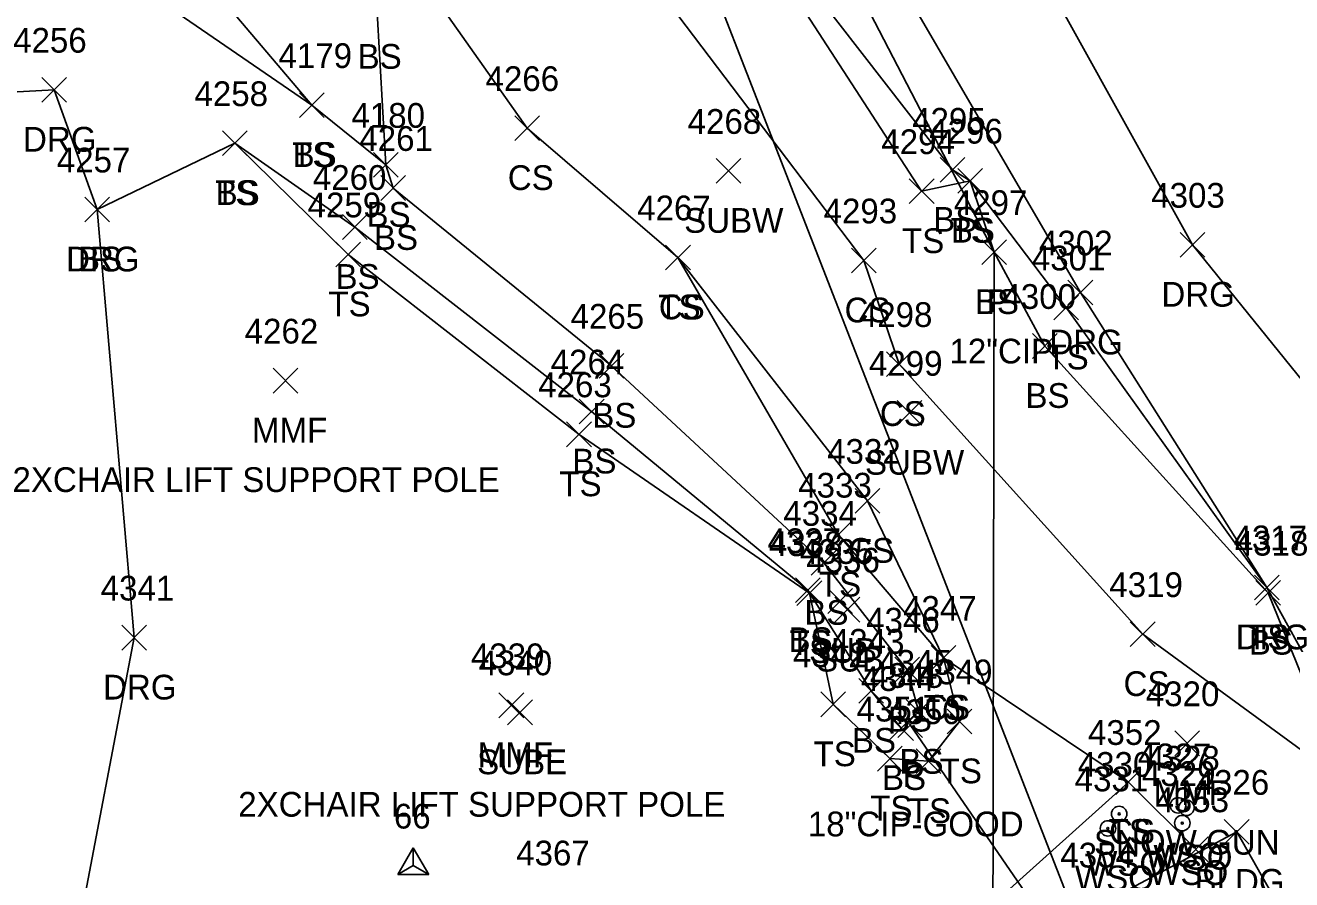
# Model space of a CAD drawing. Extents: x 49137 to 50946, y 9590 to 10709.
# Drawn here: x 50101.6 to 50204, y 10501.9 to 10570.9 of the extents above; entities that cross this region are included whole.
import ezdxf

# ---------------------------------------------------------------- set-up
doc = ezdxf.new("R2010")
doc.units = 0
for name, color, linetype in [('C_I', 7, 'Continuous'), ('CPSM', 7, 'Continuous'), ('D_A', 7, 'Continuous'), ('D_C', 7, 'Continuous'), ('D_I', 7, 'Continuous'), ('D_TIC', 7, 'Continuous'), ('DCP', 7, 'Continuous'), ('L_A', 7, 'Continuous'), ('L_C', 7, 'Continuous'), ('L_I', 7, 'Continuous'), ('L_TIC', 7, 'Continuous'), ('LBC', 7, 'Continuous'), ('LELB', 7, 'Continuous'), ('R_A', 7, 'Continuous'), ('R_I', 7, 'Continuous'), ('R_TIC', 7, 'Continuous'), ('RDG', 7, 'Continuous'), ('U_A', 7, 'Continuous'), ('U_I', 7, 'Continuous'), ('U_TIC', 7, 'Continuous'), ('UWV', 7, 'Continuous')]:
    doc.layers.add(name, color=color, linetype=linetype)

msp = doc.modelspace()

# ---------------------------------------------------------------- linework, layer by layer
at = {"layer": 'CPSM'}
for p, q in [((50131.72, 10502.3), (50132.97, 10504.46)), ((50134.22, 10502.3), (50132.97, 10504.46)), ((50132.97, 10503.02), (50132.97, 10504.46)), ((50131.72, 10502.3), (50132.97, 10503.02)), ((50132.97, 10503.02), (50132.97, 10503.02)), ((50132.97, 10503.02), (50134.22, 10502.3)), ((50131.72, 10502.3), (50134.22, 10502.3))]:
    msp.add_line(p, q, dxfattribs=at)
at = {"layer": 'D_TIC'}
for points in [[(50178.93, 10551.61), (50180.93, 10553.61)], [(50180.93, 10551.61), (50178.93, 10553.61)], [(50172.14, 10513.39), (50174.14, 10515.39)], [(50174.14, 10513.39), (50172.14, 10515.39)]]:
    msp.add_lwpolyline(points, dxfattribs=at)
at = {"layer": 'DCP'}
for points in [[(49941.69, 9827.48), (50059.34, 9808.37), (50181.4, 9733.09), (50281.74, 9743.29), (50422.72, 9892.52), (50122.34, 10663.61), (50179.93, 10552.61), (50179.64, 10394.45), (50122.34, 10285.07), (50121.56, 10284.35)], [(50173.14, 10514.39), (50224.61, 10439.45)]]:
    msp.add_lwpolyline(points, dxfattribs=at)
at = {"layer": 'L_TIC'}
for points in [[(50123.77, 10563.49), (50125.77, 10565.49)], [(50125.77, 10563.49), (50123.77, 10565.49)], [(50123.77, 10563.49), (50125.77, 10565.49)], [(50125.77, 10563.49), (50123.77, 10565.49)], [(50141.17, 10561.63), (50143.17, 10563.63)], [(50143.17, 10561.63), (50141.17, 10563.63)], [(50117.54, 10560.41), (50119.54, 10562.41)], [(50119.54, 10560.41), (50117.54, 10562.41)], [(50117.54, 10560.41), (50119.54, 10562.41)], [(50119.54, 10560.41), (50117.54, 10562.41)], [(50129.75, 10558.66), (50131.75, 10560.66)], [(50131.75, 10558.66), (50129.75, 10560.66)], [(50129.75, 10558.66), (50131.75, 10560.66)], [(50131.75, 10558.66), (50129.75, 10560.66)], [(50175.56, 10558.26), (50177.56, 10560.26)], [(50177.56, 10558.26), (50175.56, 10560.26)], [(50176.99, 10557.38), (50178.99, 10559.38)], [(50178.99, 10557.38), (50176.99, 10559.38)], [(50176.99, 10557.38), (50178.99, 10559.38)], [(50178.99, 10557.38), (50176.99, 10559.38)], [(50130.35, 10556.79), (50132.35, 10558.79)], [(50132.35, 10556.79), (50130.35, 10558.79)], [(50130.35, 10556.79), (50132.35, 10558.79)], [(50132.35, 10556.79), (50130.35, 10558.79)], [(50173.07, 10556.53), (50175.07, 10558.53)], [(50175.07, 10556.53), (50173.07, 10558.53)], [(50106.41, 10555.05), (50108.41, 10557.05)], [(50108.41, 10555.05), (50106.41, 10557.05)], [(50127.24, 10553.64), (50129.24, 10555.64)], [(50129.24, 10553.64), (50127.24, 10555.64)], [(50127.24, 10553.64), (50129.24, 10555.64)], [(50129.24, 10553.64), (50127.24, 10555.64)], [(50126.7, 10551.42), (50128.7, 10553.42)], [(50128.7, 10551.42), (50126.7, 10553.42)], [(50153.37, 10551.18), (50155.37, 10553.18)], [(50155.37, 10551.18), (50153.37, 10553.18)], [(50153.37, 10551.18), (50155.37, 10553.18)], [(50155.37, 10551.18), (50153.37, 10553.18)], [(50178.93, 10551.61), (50180.93, 10553.61)], [(50180.93, 10551.61), (50178.93, 10553.61)], [(50168.4, 10550.93), (50170.4, 10552.93)], [(50170.4, 10550.93), (50168.4, 10552.93)], [(50184.75, 10547.13), (50186.75, 10549.13)], [(50186.75, 10547.13), (50184.75, 10549.13)], [(50183.02, 10544.02), (50185.02, 10546.02)], [(50185.02, 10544.02), (50183.02, 10546.02)], [(50148, 10542.42), (50150, 10544.42)], [(50150, 10542.42), (50148, 10544.42)], [(50171.24, 10542.56), (50173.24, 10544.56)], [(50173.24, 10542.56), (50171.24, 10544.56)], [(50121.65, 10541.22), (50123.65, 10543.22)], [(50123.65, 10541.22), (50121.65, 10543.22)], [(50146.39, 10538.72), (50148.39, 10540.72)], [(50148.39, 10538.72), (50146.39, 10540.72)], [(50146.39, 10538.72), (50148.39, 10540.72)], [(50148.39, 10538.72), (50146.39, 10540.72)], [(50145.37, 10536.88), (50147.37, 10538.88)], [(50147.37, 10536.88), (50145.37, 10538.88)], [(50168.69, 10531.5), (50170.69, 10533.5)], [(50170.69, 10531.5), (50168.69, 10533.5)], [(50166.35, 10528.77), (50168.35, 10530.77)], [(50168.35, 10528.77), (50166.35, 10530.77)], [(50165.15, 10526.49), (50167.15, 10528.49)], [(50167.15, 10526.49), (50165.15, 10528.49)], [(50200.97, 10524.51), (50202.97, 10526.51)], [(50202.97, 10524.51), (50200.97, 10526.51)], [(50163.87, 10524.28), (50165.87, 10526.28)], [(50165.87, 10524.28), (50163.87, 10526.28)], [(50163.99, 10524.04), (50165.99, 10526.04)], [(50165.99, 10524.04), (50163.99, 10526.04)], [(50201.08, 10524.08), (50203.08, 10526.08)], [(50203.08, 10524.08), (50201.08, 10526.08)], [(50190.94, 10520.73), (50192.94, 10522.73)], [(50192.94, 10520.73), (50190.94, 10522.73)], [(50174.83, 10518.81), (50176.83, 10520.81)], [(50176.83, 10518.81), (50174.83, 10520.81)], [(50174.83, 10518.81), (50176.83, 10520.81)], [(50176.83, 10518.81), (50174.83, 10520.81)], [(50171.9, 10517.86), (50173.9, 10519.86)], [(50173.9, 10517.86), (50171.9, 10519.86)], [(50171.9, 10517.86), (50173.9, 10519.86)], [(50173.9, 10517.86), (50171.9, 10519.86)], [(50168.99, 10516.15), (50170.99, 10518.15)], [(50170.99, 10516.15), (50168.99, 10518.15)], [(50139.9, 10514.98), (50141.9, 10516.98)], [(50141.9, 10514.98), (50139.9, 10516.98)], [(50165.92, 10515.06), (50167.92, 10517.06)], [(50167.92, 10515.06), (50165.92, 10517.06)], [(50172.83, 10514.45), (50174.83, 10516.45)], [(50174.83, 10514.45), (50172.83, 10516.45)], [(50171.42, 10513.14), (50173.42, 10515.14)], [(50173.42, 10513.14), (50171.42, 10515.14)], [(50176.12, 10513.68), (50178.12, 10515.68)], [(50178.12, 10513.68), (50176.12, 10515.68)], [(50194.53, 10511.91), (50196.53, 10513.91)], [(50196.53, 10511.91), (50194.53, 10513.91)], [(50170.5, 10510.67), (50172.5, 10512.67)], [(50172.5, 10510.67), (50170.5, 10512.67)], [(50170.5, 10510.67), (50172.5, 10512.67)], [(50172.5, 10510.67), (50170.5, 10512.67)], [(50173.62, 10510.46), (50175.62, 10512.46)], [(50175.62, 10510.46), (50173.62, 10512.46)], [(50189.78, 10508.78), (50191.78, 10510.78)], [(50191.78, 10508.78), (50189.78, 10510.78)], [(50189.78, 10508.78), (50191.78, 10510.78)], [(50191.78, 10508.78), (50189.78, 10510.78)], [(50198.54, 10504.75), (50200.54, 10506.75)], [(50200.54, 10504.75), (50198.54, 10506.75)], [(50195.23, 10503.34), (50197.23, 10505.34)], [(50197.23, 10503.34), (50195.23, 10505.34)], [(50195.23, 10503.34), (50197.23, 10505.34)], [(50197.23, 10503.34), (50195.23, 10505.34)]]:
    msp.add_lwpolyline(points, dxfattribs=at)
at = {"layer": 'LBC'}
msp.add_lwpolyline([(50208.1, 10490.68), (50199.54, 10505.75), (50188.54, 10499.87), (50193.08, 10491.83), (50197.16, 10484.51)], dxfattribs=at)
at = {"layer": 'LELB'}
for points in [[(50019.73, 10695.53), (50037.05, 10672.19), (50068.92, 10635.88), (50093.38, 10612.86), (50116.43, 10587.84), (50130.03, 10572.43), (50130.75, 10559.66)], [(50006.39, 10686.67), (50027.96, 10663.22), (50060.02, 10630.32), (50085.34, 10605.89), (50109.29, 10582.73), (50124.77, 10564.49)], [(50121.04, 10673.8), (50125.72, 10663.25), (50118.76, 10654.2), (50121.52, 10635.5), (50130.84, 10628.15), (50141.37, 10625.76), (50142.8, 10621.81), (50131.45, 10616.61), (50128.86, 10614.81), (50135.94, 10599.09), (50146.92, 10581.6), (50169.4, 10551.93), (50172.24, 10543.56), (50191.94, 10521.73), (50208.27, 10509.79)], [(50076.58, 10639), (50087.99, 10629.91), (50097.47, 10620.46), (50116.3, 10599.61), (50123.36, 10595.45), (50134.59, 10584.36), (50132.63, 10576.14), (50142.17, 10562.63), (50154.37, 10552.18), (50169.69, 10532.5), (50175.83, 10519.81), (50190.78, 10509.78), (50196.23, 10504.34)], [(50121.52, 10635.5), (50126.1, 10622.98), (50139.03, 10624.1), (50139.75, 10622.38), (50131.45, 10616.61), (50139.21, 10602.48), (50154.46, 10587.74), (50176.56, 10559.26), (50177.99, 10558.38), (50179.93, 10552.61), (50184.02, 10545.02), (50202.08, 10525.08), (50208.27, 10509.79), (50212.74, 10492.15), (50211.87, 10488.15)], [(50142.8, 10621.81), (50144.55, 10602.94), (50154.46, 10587.74), (50174.07, 10557.53), (50177.99, 10558.38), (50185.75, 10548.13), (50201.97, 10525.51)], [(50082.1, 10581.17), (50104.18, 10578.62), (50124.77, 10564.49), (50130.75, 10559.66), (50131.35, 10557.79)], [(50107.41, 10556.05), (50118.54, 10561.41), (50128.24, 10554.64)], [(50118.54, 10561.41), (50127.7, 10552.42), (50146.37, 10537.88), (50164.99, 10525.04), (50166.92, 10516.06), (50171.5, 10511.67)], [(50131.35, 10557.79), (50149, 10543.42), (50166.15, 10527.49), (50172.9, 10518.86)], [(50128.24, 10554.64), (50147.39, 10539.72)], [(50154.37, 10552.18), (50167.35, 10529.77), (50175.83, 10519.81), (50177.12, 10514.68), (50174.62, 10511.46), (50171.5, 10511.67)], [(50147.39, 10539.72), (50164.87, 10525.28), (50169.99, 10517.15), (50172.42, 10514.14), (50173.83, 10515.45), (50172.9, 10518.86)], [(50190.78, 10509.78), (50171.63, 10492.56), (50161.69, 10491.6), (50152.32, 10490.35), (50149.76, 10480.36), (50143.58, 10468.36), (50154.45, 10456.06), (50172.98, 10448.23), (50183.27, 10447.45), (50192.18, 10443.6)]]:
    msp.add_lwpolyline(points, dxfattribs=at)
at = {"layer": 'R_TIC'}
for points in [[(50102.93, 10564.73), (50104.93, 10566.73)], [(50104.93, 10564.73), (50102.93, 10566.73)], [(50106.41, 10555.05), (50108.41, 10557.05)], [(50108.41, 10555.05), (50106.41, 10557.05)], [(50194.96, 10552.2), (50196.96, 10554.2)], [(50196.96, 10552.2), (50194.96, 10554.2)], [(50185.9, 10548.34), (50187.9, 10550.34)], [(50187.9, 10548.34), (50185.9, 10550.34)], [(50200.97, 10524.51), (50202.97, 10526.51)], [(50202.97, 10524.51), (50200.97, 10526.51)], [(50109.4, 10520.45), (50111.4, 10522.45)], [(50111.4, 10520.45), (50109.4, 10522.45)]]:
    msp.add_lwpolyline(points, dxfattribs=at)
at = {"layer": 'RDG'}
for points in [[(50119.02, 10699.76), (50135.14, 10671.06), (50153.64, 10632.53), (50170.9, 10598.36), (50195.96, 10553.2), (50209.41, 10536.57), (50218.43, 10521.85), (50227.96, 10501.32), (50227.51, 10456.11), (50228.06, 10435.89), (50234.37, 10417.11), (50265.83, 10427.19)], [(50110.8, 10693.82), (50121.04, 10673.8), (50126.58, 10664.65), (50145.31, 10626.1), (50162.07, 10592.03), (50186.9, 10549.34), (50201.97, 10525.51), (50210.44, 10510.19), (50215.05, 10493.61), (50214.49, 10487.12), (50214.47, 10480.19), (50214.66, 10477.36), (50207.53, 10457)], [(50095.25, 10547.5), (50093.45, 10565.17), (50103.93, 10565.73), (50107.41, 10556.05), (50110.4, 10521.45), (50105.68, 10496.74), (50106.96, 10485.77), (50113.12, 10471.78), (50124.76, 10458.74), (50147.1, 10444.79), (50157.25, 10438.91), (50175.59, 10435.41), (50187.55, 10433.23), (50196.81, 10438.28), (50207.53, 10457)]]:
    msp.add_lwpolyline(points, dxfattribs=at)
at = {"layer": 'U_TIC'}
for points in [[(50157.46, 10558.17), (50159.46, 10560.17)], [(50159.46, 10558.17), (50157.46, 10560.17)], [(50172.08, 10538.62), (50174.08, 10540.62)], [(50174.08, 10538.62), (50172.08, 10540.62)], [(50166.49, 10523.41), (50168.49, 10525.41)], [(50168.49, 10523.41), (50166.49, 10525.41)], [(50167.06, 10522.71), (50169.06, 10524.71)], [(50169.06, 10522.71), (50167.06, 10524.71)], [(50140.6, 10514.41), (50142.6, 10516.41)], [(50142.6, 10514.41), (50140.6, 10516.41)]]:
    msp.add_lwpolyline(points, dxfattribs=at)
at = {"layer": 'UWV'}
for centre, radius in [((50194.8, 10507.89), 0.625), ((50194.8, 10507.89), 0.0833), ((50195.48, 10507.7), 0.625), ((50190.04, 10507.2), 0.625), ((50190.04, 10507.2), 0.0833), ((50195.14, 10506.46), 0.625), ((50195.48, 10507.7), 0.0833), ((50189.13, 10506.03), 0.625), ((50189.13, 10506.03), 0.0833), ((50195.14, 10506.46), 0.0833)]:
    msp.add_circle(centre, radius, dxfattribs=at)

# ---------------------------------------------------------------- texts
at = {"layer": 'C_I'}
msp.add_text('66', height=2, dxfattribs=at).set_placement((50131.4, 10506.02))
at = {"layer": 'D_A'}
for p in [(50179.31, 10547.61), (50172.52, 10509.39)]:
    msp.add_text('P', height=2, dxfattribs=at).set_placement(p)
at = {"layer": 'D_C'}
for s, p in [('12"CIP', (50176.32, 10543.61)), ('18"CIP-GOOD', (50164.87, 10505.39))]:
    msp.add_text(s, height=2, dxfattribs=at).set_placement(p)
at = {"layer": 'D_I'}
for s, p in [('4297', (50176.67, 10555.61)), ('4348', (50169.88, 10517.39))]:
    msp.add_text(s, height=2, dxfattribs=at).set_placement(p)
at = {"layer": 'L_A'}
for s, p in [('BS', (50128.47, 10567.43)), ('TS', (50123.18, 10559.49)), ('BS', (50123.21, 10559.49)), ('CS', (50140.61, 10557.63)), ('TS', (50116.95, 10556.41)), ('BS', (50116.99, 10556.41)), ('BS', (50129.19, 10554.66)), ('BS', (50129.19, 10554.66)), ('BS', (50175, 10554.26)), ('TS', (50176.4, 10553.38)), ('BS', (50176.43, 10553.38)), ('BS', (50129.79, 10552.79)), ('BS', (50129.79, 10552.79)), ('TS', (50172.48, 10552.53)), ('BS', (50105.86, 10551.05)), ('BS', (50126.68, 10549.64)), ('BS', (50126.68, 10549.64)), ('TS', (50126.11, 10547.42)), ('TS', (50152.78, 10547.18)), ('CS', (50152.82, 10547.18)), ('CS', (50167.84, 10546.93)), ('BS', (50178.37, 10547.61)), ('TS', (50184.16, 10543.13)), ('BS', (50182.46, 10540.02)), ('BS', (50147.44, 10538.42)), ('CS', (50170.69, 10538.56)), ('MMF', (50119.93, 10537.22)), ('BS', (50145.83, 10534.72)), ('BS', (50145.83, 10534.72)), ('TS', (50144.78, 10532.88)), ('CS', (50168.13, 10527.5)), ('TS', (50165.76, 10524.77)), ('BS', (50164.59, 10522.49)), ('BS', (50163.31, 10520.28)), ('TS', (50200.38, 10520.51)), ('TS', (50163.4, 10520.04)), ('BS', (50200.52, 10520.08)), ('CS', (50190.39, 10516.73)), ('TS', (50174.24, 10514.81)), ('CS', (50174.27, 10514.81)), ('BS', (50171.34, 10513.86)), ('BS', (50171.34, 10513.86)), ('BS', (50168.43, 10512.15)), ('TS', (50165.33, 10511.06)), ('MMF', (50138.18, 10510.98)), ('BS', (50172.27, 10510.45)), ('BS', (50170.86, 10509.14)), ('TS', (50175.53, 10509.68)), ('MMF', (50192.82, 10507.91)), ('TS', (50169.91, 10506.67)), ('TS', (50169.91, 10506.67)), ('TS', (50173.03, 10506.46)), ('TS', (50189.19, 10504.78)), ('CS', (50189.22, 10504.78)), ('BLDG', (50196.13, 10500.75))]:
    msp.add_text(s, height=2, dxfattribs=at).set_placement(p)
at = {"layer": 'L_C'}
for s, p in [('2XCHAIR LIFT SUPPORT POLE', (50100.57, 10533.22)), ('2XCHAIR LIFT SUPPORT POLE', (50118.82, 10506.98)), ('SNOW GUN', (50188, 10503.91))]:
    msp.add_text(s, height=2, dxfattribs=at).set_placement(p)
at = {"layer": 'L_I'}
for s, p in [('4179', (50122.07, 10567.49)), ('4179', (50122.07, 10567.49)), ('4266', (50138.81, 10565.63)), ('4258', (50115.28, 10564.41)), ('4258', (50115.28, 10564.41)), ('4180', (50127.97, 10562.66)), ('4180', (50127.97, 10562.66)), ('4295', (50173.3, 10562.26)), ('4296', (50174.68, 10561.38)), ('4296', (50174.68, 10561.38)), ('4261', (50128.61, 10560.79)), ('4261', (50128.61, 10560.79)), ('4294', (50170.81, 10560.53)), ('4257', (50104.15, 10559.05)), ('4260', (50124.85, 10557.64)), ('4260', (50124.85, 10557.64)), ('4259', (50124.43, 10555.42)), ('4267', (50151.07, 10555.18)), ('4267', (50151.07, 10555.18)), ('4297', (50176.67, 10555.61)), ('4293', (50166.14, 10554.93)), ('4301', (50182.98, 10551.13)), ('4300', (50180.6, 10548.02)), ('4265', (50145.69, 10546.42)), ('4298', (50168.99, 10546.56)), ('4262', (50119.34, 10545.22)), ('4264', (50144.08, 10542.72)), ('4264', (50144.08, 10542.72)), ('4263', (50143.07, 10540.88)), ('4332', (50166.43, 10535.5)), ('4333', (50164.09, 10532.77)), ('4334', (50162.89, 10530.49)), ('4317', (50199.28, 10528.51)), ('4337', (50161.61, 10528.28)), ('4338', (50161.73, 10528.04)), ('4318', (50199.39, 10528.08)), ('4319', (50189.24, 10524.73)), ('4347', (50172.57, 10522.81)), ('4347', (50172.57, 10522.81)), ('4346', (50169.58, 10521.86)), ('4346', (50169.58, 10521.86)), ('4343', (50166.73, 10520.15)), ('4339', (50137.63, 10518.98)), ('4342', (50163.67, 10519.06)), ('4345', (50170.57, 10518.45)), ('4349', (50173.85, 10517.68)), ('4344', (50169.16, 10517.14)), ('4320', (50192.19, 10515.91)), ('4351', (50168.81, 10514.67)), ('4351', (50168.81, 10514.67)), ('4350', (50171.28, 10514.46)), ('4352', (50187.52, 10512.78)), ('4352', (50187.52, 10512.78)), ('4326', (50196.22, 10508.75)), ('4353', (50192.97, 10507.34)), ('4353', (50192.97, 10507.34)), ('4367', (50141.29, 10503.04)), ('4354', (50185.28, 10502.87))]:
    msp.add_text(s, height=2, dxfattribs=at).set_placement(p)
at = {"layer": 'R_A'}
for p in [(50101.42, 10560.73), (50104.9, 10551.05), (50193.45, 10548.2), (50184.39, 10544.34), (50199.46, 10520.51), (50107.89, 10516.45)]:
    msp.add_text('DRG', height=2, dxfattribs=at).set_placement(p)
at = {"layer": 'R_I'}
for s, p in [('4256', (50100.62, 10568.73)), ('4257', (50104.15, 10559.05)), ('4303', (50192.63, 10556.2)), ('4302', (50183.56, 10552.34)), ('4317', (50199.28, 10528.51)), ('4341', (50107.7, 10524.45))]:
    msp.add_text(s, height=2, dxfattribs=at).set_placement(p)
at = {"layer": 'U_A'}
for s, p in [('SUBW', (50154.87, 10554.17)), ('SUBW', (50169.49, 10534.62)), ('SUB', (50164.97, 10519.41)), ('SUB', (50165.53, 10518.71)), ('SUBE', (50138.13, 10510.41)), ('WSO', (50192.13, 10502.89)), ('WSO', (50187.37, 10502.2)), ('WSO', (50192.81, 10502.7)), ('WSO', (50186.46, 10501.03)), ('WSO', (50192.47, 10501.46))]:
    msp.add_text(s, height=2, dxfattribs=at).set_placement(p)
at = {"layer": 'U_I'}
for s, p in [('4268', (50155.15, 10562.17)), ('4299', (50169.81, 10542.62)), ('4335', (50164.23, 10527.41)), ('4336', (50164.74, 10526.71)), ('4340', (50138.25, 10518.41)), ('4330', (50186.69, 10510.2)), ('4327', (50191.54, 10510.89)), ('4328', (50192.22, 10510.7)), ('4331', (50186.44, 10509.03)), ('4329', (50191.88, 10509.46))]:
    msp.add_text(s, height=2, dxfattribs=at).set_placement(p)

doc.saveas('drawing.dxf')
